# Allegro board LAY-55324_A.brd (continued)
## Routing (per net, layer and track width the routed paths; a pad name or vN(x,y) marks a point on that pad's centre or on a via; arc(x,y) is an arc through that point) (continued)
GPIO_AD_B1_12_EXT: length 38.3
  TOP w0.102: v1(41.33,52.58) 40.24,52.58 J64.5 ; v1(74.93,49.4) J3.31
  BOTTOM w0.102: v1(74.93,49.4) 74.52,49.81 74.52,50.06 72.31,52.27 65.48,52.27 64.97,52.79 64.12,52.79 63.91,52.58 v1(41.33,52.58)
GPIO_AD_B1_13: length 21
  TOP w0.102: v1(147.37,49.28) 146.41,48.31 146.41,45.32 145.97,44.89 145.97,40.77 v1(145.97,39.88)
  TOP w0.127: U4.H11 v3(146.23,31.43)
  BOTTOM w0.102: J2.27 147.5,48.9 v1(147.37,49.28) ; v3(146.23,31.43) 146.46,31.66 146.46,32.41 147.02,32.97 147.02,38.84 v1(145.97,39.88)
GPIO_AD_B1_13_EXT: length 41.6
  TOP w0.102: v1(36.32,52.42) J64.9 ; v1(73.66,49.4) J3.27
  BOTTOM w0.102: v1(36.32,52.42) 36.72,52.02 63.53,52.02 63.75,51.79 71.27,51.79 v1(73.66,49.4)
GPIO_AD_B1_15: length 23.3
  TOP w0.102: v1(148.77,53.47) 149.23,53.01 149.23,48.34 149.12,48.23 149.12,46.18 149.43,45.87 149.43,44.88 148.87,44.32 148.44,44.32 147.47,43.36 147.47,39.11 147.42,39.06 147.42,39.05 147.4,39.02 147.4,37.11 147.2,36.92 U4.J14
  BOTTOM w0.102: J2.32 v1(148.77,53.47)
GPIO_AD_B1_15_EXT: length 41.2
  TOP w0.102: J3.32 74.93,53.87 74.07,54.74 38.07,54.74 37.54,54.2 J64.7
GPIO_B0_04: length 23.9
  TOP w0.102: SW62.2 v1(134.89,18.54) SW62.1 134.89,21.72 135.31,22.14 135.31,22.73 137.46,24.89 137.46,25.78 138.61,26.92 138.99,26.92 R37.2 140.63,27.56 141.9,28.83 142.87,28.83 143.2,29.15 U4.C8
  BOTTOM w0.102: 134.89,17.53 v1(134.89,18.54)
GPIO_B0_05: length 13.9
  TOP w0.102: J63.2 133.02,26.16 134.29,27.43 134.29,27.44 134.34,27.49 134.34,28.39 134.92,28.97 141.01,28.97 141.52,29.48 142.11,29.48 142.43,29.15 U4.B8
GPIO_B0_06: length 3.6
  TOP w0.102: R35.2 v1(140.51,28.45) 141,28.45 141.71,29.15 U4.A8
  BOTTOM w0.102: R35.2 v1(140.51,28.45)
GPIO_B0_07: length 3.4
  TOP w0.102: U4.A9 141.35,29.8 141.14,29.59 v1(140.51,29.59) R38.2
  BOTTOM w0.102: R38.2 v1(140.51,29.59)
GPIO_B0_08: length 4.5
  TOP w0.102: U4.B9 142.65,29.91 142.33,30.24 142.33,30.56 142.11,30.78 141.61,30.78 R36.2
GPIO_B0_09: length 20.3
  TOP w0.102: SW61.1 v1(134.89,38.23) 135.25,37.86 135.25,31.36 SW61.2 135.27,30.61 137.34,30.61 137.79,31.06 139.4,31.06 139.62,30.84 R42.2 140.77,30.48 141.12,30.13 142.11,30.13 142.31,29.93 142.31,29.66 142.49,29.48 142.98,29.48 U4.C9
  BOTTOM w0.102: C37.1 134.92,38.77 134.89,38.73 v1(134.89,38.23)
GPIO_B0_10: length 33.3
  TOP w0.102: R39.2 v1(140.51,33.78)
  TOP w0.127: U4.D9 v3(143.63,29.48)
  BOTTOM w0.102: v3(143.63,29.48) 142.66,29.48 141.99,30.15 141.99,31.7 141.15,32.53 140.83,33.3 v1(140.51,33.78) 139.09,35.2 137.04,35.2 133.17,31.34 133.17,16.23 R227.2
GPIO_B0_11: length 28.5
  TOP w0.102: v1(141.15,50.81) 140.47,50.13 139.92,50.13 139.45,49.66 139.45,49.1 137.46,47.12 137.46,45.27 136.19,44 136.19,32.77 136.72,32.25 139,32.25 R34.2 139.64,31.61 140.27,31.61 141.43,30.45 U4.A10
  BOTTOM w0.102: J2.8 v1(141.15,50.81)
GPIO_B0_11_EXT: length 33.4
  TOP w0.102: J3.8 67.31,51.05 v1(66.93,50.67) ; v1(66.93,35.05) 63.75,35.05 62.23,36.58 v1(52.58,36.58)
  BOTTOM w0.102: v1(66.93,50.67) v1(66.93,35.05) ; R235.2 v1(52.58,36.58)
GPIO_B0_12: length 10.3
  TOP w0.102: R41.2 v1(140.51,34.8) ; U4.C10 v3(143.63,30.13)
  BOTTOM w0.102: R78.2 140,34.8 v1(140.51,34.8) 141.15,34.16 141.15,33.43 141.35,32.95 142.39,31.9 142.39,30.07 142.71,29.75 143.25,29.75 v3(143.63,30.13)
GPIO_B0_13: length 7.9
  TOP w0.102: R31.2 v1(140.51,35.81)
  TOP w0.127: U4.D10 v3(143.63,30.78)
  BOTTOM w0.102: v1(140.51,35.81) 140.89,35.81 141.4,35.31 141.4,34.92 143.15,33.18 143.15,31.26 v3(143.63,30.78)
GPIO_B0_14: length 26.4
  TOP w0.102: R18.2 v1(140.51,36.83) 140.51,37.26 139.32,38.46 139.32,46.73 141.72,49.13 141.72,49.47 v1(143.05,50.81) ; U4.E10 v3(144.28,30.78)
  BOTTOM w0.102: J2.14 v1(143.05,50.81) ; v3(144.28,30.78) 144.09,30.97 143.98,30.97 143.61,31.33 143.61,33.22 141.76,35.08 141.76,35.59 v1(140.51,36.83)
GPIO_B0_14_EXT: length 47.9
  TOP w0.102: v1(65.91,21.46) 64.01,19.56 53.34,19.56 52.45,18.67 U213.2 ; v1(69.22,50.67) J3.14
  BOTTOM w0.102: v1(65.91,21.46) 65.91,27.56 68.96,30.61 68.96,49.53 69.22,49.78 v1(69.22,50.67)
GPIO_B0_15: length 17.2
  TOP w0.102: v1(142.16,35.25) 142.16,34.42 142.42,34.16 142.42,33.4 142.33,33.31 142.33,32.91 142.49,32.75 142.74,32.75 142.96,32.53 142.96,32.32 143.18,32.1 143.39,32.1 143.61,31.88 143.61,31.67 143.83,31.45 144.15,31.45 144.5,31.1 U4.E11
  BOTTOM w0.102: U214.3 v4(135.33,36.01) 135.88,36.01 137.87,38 139.85,38 140.51,37.34 140.89,37.34 R77.2 v1(142.16,35.25)
GPIO_B1_00: length 60.3
  TOP w0.102: R224.2 v1(161.72,8.89) ; v1(140.51,32.64) 141.02,32.13 141.02,31.87 141.79,31.1 U4.A11
  BOTTOM w0.102: v1(140.51,32.64) 138.96,34.19 136.6,34.19 133.91,31.5 133.91,20.57 137.46,17.02 137.46,9.78 138.1,9.14 139.9,9.14 140.84,8.2 145.62,8.2 146.18,8.76 147.02,8.76 147.57,8.2 160.15,8.2 160.83,8.89 v1(161.72,8.89)
GPIO_B1_02: length 24.3
  TOP w0.102: v1(141.15,49.27) 138.94,47.06 138.94,45.19 137.46,43.71 137.46,39.24 v1(139.12,37.59) ; U4.C11 v3(142.98,30.78)
  BOTTOM w0.102: J2.7 v1(141.15,49.27) ; v1(139.12,37.59) 139.83,36.88 139.83,35.71 140.23,35.31 140.61,35.31 141.55,34.37 141.55,33.52 141.77,33.01 142.72,32.05 142.72,31.03 v3(142.98,30.78)
GPIO_B1_02_EXT: length 29.2
  TOP w0.102: J64.3 42.62,51.49 43.81,50.29 46.35,50.29 47.68,51.61 63.83,51.61 65.91,49.53 66.95,49.53 67.31,49.17 J3.7
GPIO_B1_03: length 20.8
  TOP w0.102: v1(141.08,46.48) 139.76,45.16 139.76,38.62 140.92,37.46 140.92,32.93 141.35,32.5 141.35,31.97 141.88,31.45 143.5,31.45 143.85,31.1 U4.D11
  BOTTOM w0.102: J2.9 141.78,46.58 141.68,46.48 v1(141.08,46.48)
GPIO_B1_03_EXT: length 35.7
  TOP w0.102: v1(67.94,45.97) J3.9 ; J64.4 43.18,46.52 43.18,45.39 43.28,45.29 54.02,45.29 57.51,41.81 64.07,41.81 65.34,40.54 v1(67.69,40.54)
  BOTTOM w0.102: v1(67.94,45.97) 67.94,42.67 67.69,42.42 v1(67.69,40.54)
I2C1_SCL: length 22.2
  TOP w0.102: v1(149.66,49.4) 150.16,48.9 150.16,44.12 149.53,43.48 149.53,41.81 148.95,41.23 v2(148.64,40.77)
  TOP w0.127: U4.J11 v3(147.53,31.43)
  BOTTOM w0.102: v1(149.66,49.4) 149.4,49.15 J2.33 ; v3(147.53,31.43) 147.95,31.85 147.95,40.08 v2(148.64,40.77) R16.2
I2C1_SCL_EXT: length 51.6
  TOP w0.102: v1(74.14,39.75) 73.69,39.29 65.07,39.29 63.63,40.74 57.06,40.74 53.58,44.22 36.85,44.22 35,46.08 J64.10 ; v1(75.31,45.97) 75.56,46.23 J3.33
  BOTTOM w0.102: v1(74.14,39.75) 74.14,40.77 74.45,41.07 74.45,41.23 75.06,41.84 75.06,45.36 v1(75.31,45.97)
I2C1_SDA: length 20.4
  TOP w0.102: U4.K11 v3(147.53,30.78) ; v1(150.67,46.61) 150.67,44.04 149.91,43.28 149.91,41.66 149.16,40.91 149.16,38.37 v2(148.64,37.85)
  BOTTOM w0.102: v3(147.53,30.78) 148.15,30.78 148.69,31.32 148.69,35.71 148.89,35.92 148.89,37.59 v2(148.64,37.85) R15.2 ; J2.37 v1(150.67,46.61)
I2C1_SDA_EXT: length 55.9
  TOP w0.102: v1(76.2,45.97) 76.45,45.97 76.83,46.36 J3.37 ; J64.12 32.46,46.15 34.75,43.87 53.44,43.87 56.92,40.39 63.48,40.39 64.93,38.94 74.63,38.94 v1(74.85,39.17)
  BOTTOM w0.102: v1(74.85,39.17) 75.31,39.62 75.31,41.02 75.82,41.53 75.82,45.09 76.2,45.47 v1(76.2,45.97)
JTAG_NTRST: length 19.5
  TOP w0.102: v1(145.09,38.43) 145.09,42.3 145.29,42.49 145.29,43.36 144.96,43.69 144.96,45.54 145.47,46.05 v1(145.47,46.61)
  TOP w0.127: U4.G10 v3(145.58,30.78)
  BOTTOM w0.102: v1(145.09,38.43) 145.09,37.81 146.23,36.68 146.23,33.02 145.9,32.69 145.9,32 145.58,31.68 v3(145.58,30.78) ; J2.23 146.23,46.74 146.1,46.61 v1(145.47,46.61)
JTAG_NTRST_EXT: length 64.9
  TOP w0.102: v1(72.01,49.4) 72.39,49.02 J3.23 ; v1(72.14,41.27) 71.35,40.49 70.09,40.49 69.1,41.48 65.4,41.48 64.36,42.52 57.94,42.52 57.28,43.18 57.28,43.18 51.33,49.12 23.76,49.12 23.15,48.51 J62.9
  BOTTOM w0.102: v1(72.14,41.27) 71.5,41.91 71.5,47.5 72.01,48.01 v1(72.01,49.4)
JTAG_TDI: length 16.6
  TOP w0.102: U4.F14 145.25,33.69 145.36,33.8 145.36,34.53 144.93,34.97 144.93,36.15 144.81,36.27 144.81,37.55 144.12,38.24 144.12,41.15 143.31,41.96 143.31,44.97 144.58,46.24 v1(144.58,46.61)
  BOTTOM w0.102: J2.19 144.96,46.71 144.86,46.61 v1(144.58,46.61)
JTAG_TDI_EXT: length 57.4
  TOP w0.102: v1(71.12,49.4) J3.19 ; v1(20.57,54.61) 20.57,52.58
  BOTTOM w0.102: v1(71.12,49.4) 71.12,50.98 70.82,51.28 23.9,51.28 v1(20.57,54.61)
JTAG_TDO: length 23.9
  TOP w0.102: U4.G13 145.9,32.51 146.25,32.85 146.25,35.16 146.05,35.36 146.05,37.49 146.23,37.67 146.23,39.37 146.41,39.55 146.41,44.7 146.76,45.06 146.76,47.9 147.88,49.02 147.88,49.94 148.34,50.39 148.34,51.31 147.88,51.77 v1(147.88,53.47)
  BOTTOM w0.102: v1(147.88,53.47) 148.13,53.21 J2.30
JTAG_TDO_EXT: length 70.8
  TOP w0.102: J3.30 74.3,50.93 v1(74.55,50.67) ; v1(74.55,42.42) 74.04,42.93 64.96,42.93 64.66,43.23 58.37,43.23 51.77,49.83 23.7,49.83 22.96,50.57 20.32,50.57 19.3,51.59 19.3,52.58
  BOTTOM w0.102: v1(74.55,50.67) 75.44,49.79 75.44,48.9 74.8,48.26 74.8,45.75 74.7,45.5 74.7,43.08 74.55,42.93 v1(74.55,42.42)
MIC_CLK_EXT: length 31.1
  BOTTOM w0.102: J2.70 160.83,50.98 160.5,50.65 158.95,50.65 158.19,49.89 150.96,49.89 150.3,50.55 148.62,50.55 148.01,49.94 139.69,49.94 137.51,47.75 134.67,47.75 134.29,48.13 R223.1
MIC_CLK_EXT_E: length 52.5
  TOP w0.102: v1(87.25,50.67) 86.99,50.93 J3.70 ; R222.1 R365.2 53.85,40.77 55.04,39.57 63.29,39.57 64.63,38.23 76.96,38.23 77.72,38.99 v1(87.25,38.99)
  BOTTOM w0.102: v1(87.25,50.67) 87.25,50.16 88.16,49.25 88.16,42.93 88.65,42.44 88.65,41.53 88.16,41.05 88.16,39.9 v1(87.25,38.99)
MIC_DATA0_EXT: length 44.5
  TOP w0.102: R225.1 160.83,15.94 160.26,16.51 160.26,20 160.83,20.57 163.12,20.57 163.67,21.12 163.67,46.31 161.27,48.71 161.27,51.76 v1(159.56,53.47)
  BOTTOM w0.102: J2.66 v1(159.56,53.47)
MIC_DATA0_EXT_E: length 97
  TOP w0.102: v1(87.25,40.01) 86.74,39.5 77.39,39.5 76.48,38.58 64.78,38.58 63.43,39.93 56.59,39.93 53.09,43.43 34.27,43.43 32.47,45.24 22.4,45.24 21.67,45.97 16.64,45.97 14.12,48.49 14.12,51.59 14.02,51.69 R243.2 R368.2 ; v1(85.98,50.67) 85.72,50.93 J3.66
  BOTTOM w0.102: v1(87.25,40.01) 87.63,40.39 87.63,49.28 86.94,49.96 86.69,49.96 v1(85.98,50.67)
MIC_DATA1_EXT: length 74.2
  TOP w0.102: v1(133.61,51.99) 133.61,48.8 134.16,48.25 134.16,45.64 132.64,44.12 132.64,39.56 132.61,39.54 132.61,39.2 132.64,39.18 132.64,38.1 132.72,38.02 132.72,36.84 132.64,36.76 132.64,27.29 131.42,26.08 131.42,21.8 132.36,20.86 132.36,10.71 133.27,9.8 v1(133.27,8.89)
  BOTTOM w0.102: R229.1 v1(133.27,8.89) ; J2.64 158.93,51.13 158.04,50.24 151.1,50.24 150.44,50.9 148.47,50.9 147.86,50.29 139,50.29 137.31,51.99 v1(133.61,51.99)
MIC_DATA1_EXT_E: length 113.6
  TOP w0.102: R367.2 R228.2 8.25,6.73 8.25,6.98 8.51,7.24 8.89,7.24 16.56,14.91 54.79,14.91 58.8,18.92 64.26,18.92 65.94,20.6 68.4,20.6 68.53,20.47 69.37,20.47 69.49,20.6 73.79,20.6 76.5,23.32 80.85,23.32 v1(82.8,25.27) ; v1(85.09,50.67) J3.64
  BOTTOM w0.102: v1(85.09,50.67) 85.72,50.04 85.72,47.44 86.44,46.73 86.44,41.2 86.6,41.04 86.6,29.07 v1(82.8,25.27)
MIKROBUS_PWM: length 18.1
  TOP w0.102: v1(142.37,46.53) 140.47,44.62 140.47,41.14 142.34,39.27 142.34,36.09 142.96,35.47 142.96,32.85 143.3,32.51 U4.C13
  BOTTOM w0.102: J2.13 142.98,47.86 142.98,46.66 142.84,46.53 v1(142.37,46.53)
MIKROBUS_PWM_EXT: length 34.9
  TOP w0.102: J3.13 69.22,46.23 v1(69.47,45.97) ; v1(69.47,40.54) 68.88,41.12 65.26,41.12 64.22,42.16 57.8,42.16 57.24,42.72 57.23,42.72 54.11,45.85 45.26,45.85 45.16,45.95 J64.2
  BOTTOM w0.102: v1(69.47,40.54) v1(69.47,45.97)
MODE0: length 3.6
  TOP w0.102: v1(135.56,24.51) J63.3
  BOTTOM w0.102: R65.2 v1(135.56,24.51)
MODE1: length 3.6
  TOP w0.102: v1(130.48,24.51) J63.1
  BOTTOM w0.102: R70.2 v1(130.48,24.51)
MQS_LEFT: length 29.2
  TOP w0.102: v1(137.08,31.75) 136.53,31.75 135.84,32.44 135.84,44.15 136.96,45.26 v1(136.96,45.85) ; U4.E7 144.26,28.16 143.83,28.16 143.65,27.98 143.65,27.77 143.41,27.53 v3(142.98,27.53)
  BOTTOM w0.102: v1(137.08,31.75) 137.79,31.04 139.9,31.04 141.02,29.92 141.02,29.49 v3(142.98,27.53) ; J2.1 139.24,46.93 139.08,46.76 137.87,46.76 v1(136.96,45.85)
MQS_LEFT_EXT: length 66.7
  TOP w0.102: J3.1 65.41,45.59 66.12,44.88 77.81,44.88 78.72,43.97 87.22,43.97 88.8,42.39 88.8,40.74 v1(89.66,39.88)
  BOTTOM w0.102: v1(89.66,39.88) 89.28,39.5 89.28,5.59 89.98,4.89 90.83,4.89 90.93,4.99 R43.2
MQS_RIGHT: length 27.3
  TOP w0.102: v1(137.97,45.85) 137.97,45.27 136.7,44 136.7,34.16 136.55,34.01 136.55,33.17 v1(136.96,32.77) ; v3(142.98,28.18) 143.52,28.18 143.77,28.43 U4.D7
  BOTTOM w0.102: v1(137.97,45.85) 138.51,46.39 140.23,46.39 140.51,46.67 J2.5 ; v3(142.98,28.18) 141.35,29.81 141.35,30.33 140.08,31.6 138.91,31.6 138.3,32.21 137.52,32.21 v1(136.96,32.77)
MQS_RIGHT_EXT: length 66.9
  TOP w0.102: J3.5 66.67,45.59 67.03,45.24 77.95,45.24 78.87,44.32 87.37,44.32 89.15,42.54 89.15,41.15 89.41,40.89 v1(89.66,40.89)
  BOTTOM w0.102: R44.2 90.93,4.34 90.83,4.45 89.79,4.45 88.82,5.42 88.82,40.05 v1(89.66,40.89)
NVCC_SEMC_1V8_3V3: length 1.7
  TOP w0.254: U4.E6 v3(144.93,27.53) ; U4.F5 v3(144.93,26.88)
  BOTTOM w0.254: C98.1 144.76,26.3 144.93,26.46 v3(144.93,26.88)
  vias: v4(142.6,26.21)
OUT+: length 2.6
  BOTTOM w0.508: U6.C3 99.24,6.53 99.75,6.53 FB3.1
OUT-: length 2.6
  BOTTOM w0.508: U6.A3 99.21,2.64 99.73,2.64 FB4.1
OUTN: length 4.6
  BOTTOM w0.508: TP61.1 102.71,3.87 C32.1 101.27,3.8 FB4.2
OUTP: length 14.2
  BOTTOM w0.508: FB3.2 101.27,5.34 C31.1 106.11,5.27 108.2,3.17 TP63.1
POR_B: length 59.7
  TOP w0.102: v1(135.61,45.85) 135.94,46.18 135.94,46.75 136.92,47.73 137.41,47.73 138.94,49.26 138.94,49.75 139.88,50.69 v1(139.88,50.81) ; TP214.1 156.9,37.49 155.88,38.5 v1(155.88,41.55)
  TOP w0.127: U4.M7 v3(148.83,28.18)
  BOTTOM w0.102: C4.1 R1.1 ; R1.1 135.69,44.55 135.61,44.63 v1(135.61,45.85) ; R1.1 149.1,43.94 151.49,41.55 v1(155.88,41.55) ; R69.2 157.82,35.52 TP214.1 ; v3(148.83,28.18) 148.83,27.63 149.73,26.72 151.56,26.72 152.4,27.56 155.22,27.56 156.24,28.57 156.24,28.62 157.53,29.91 157.53,34.01 156.9,34.65 TP214.1 ; C74.1 157.75,37.08 157.53,37.08 TP214.1 ; J2.4 v1(139.88,50.81)
POR_B_E: length 48.8
  TOP w0.102: v1(66.04,54.1) J3.4 ; v1(22.66,54.86) TP1.1 21.84,52.58
  BOTTOM w0.102: v1(66.04,54.1) 65.86,54.28 45.95,54.28 45.59,53.92 23.6,53.92 v1(22.66,54.86)
PSRAM_CLK: length 12.2
  TOP w0.102: U4.D2 143.62,24.92 143.62,24.23 143.52,24.13 143.13,24.13 141.82,22.83 141.82,22.68 141.94,22.56 142.09,22.56 143.17,23.64 143.87,23.64 143.98,23.54 143.98,23.4 143.7,23.12 143.7,22.87 144.03,22.54 144.03,22.39 144.13,22.28 144.25,22.28 144.36,22.18 144.36,21.98 144.25,21.88 143.71,21.88 143.61,21.78 143.61,21.46 143.71,21.36 v1(144.59,21.36)
  BOTTOM w0.102: R277.2 R279.1 v1(144.59,21.36)
PSRAM_DATA0: length 11
  TOP w0.102: U4.B3 142.34,25.59 141.76,25.59 141.33,25.16 141.15,24.71 139.7,21.22 139.18,20.7 139.18,19.95 139.32,19.62 v1(140.59,18.36)
  BOTTOM w0.102: R264.1 v1(140.59,18.36)
  BOTTOM w0.127: R265.1 v1(140.59,18.36)
PSRAM_DATA1: length 9.6
  TOP w0.102: U4.A2 141.76,25.25 141.66,25.15 141.66,25.02 141.76,24.92 142.78,24.92 142.97,24.74 142.97,24.42 141.92,23.37 141.69,23.37 141.58,23.27 141.58,23.03 141.02,22.47 141.02,21.95 141.12,21.84 141.4,21.84 141.76,22.21 141.97,22.21 142.09,22.09 142.09,21.47 141.99,21.37 v1(141.6,21.37)
  BOTTOM w0.102: R273.1 141.6,21.37 v1(141.6,21.37) R266.1
PSRAM_DATA2: length 12.8
  TOP w0.102: U4.D1 143.95,24.29 144.54,22.86 145.01,21.74 145.01,20.95 145.49,19.8 146,18.57 146,17.27 145.89,17.01 145.36,16.48 144.98,16.48 144.59,16.87 v1(144.59,17.36)
  BOTTOM w0.102: R274.1 144.1,15.59 R267.1
  BOTTOM w0.127: R267.1 144.1,16.87 v1(144.59,17.36)
PSRAM_DATA3: length 12.9
  TOP w0.102: U4.E1 145.31,22.9 145.34,22.87 145.67,22.07 145.67,21 145.76,20.79 146.1,20.45 146.33,19.89 146.33,17.22 146.17,16.83 145.47,16.13 144.85,16.13 v1(143.59,16.36)
  BOTTOM w0.102: R275.1 143.6,15.2 R268.1
  BOTTOM w0.127: R268.1 143.6,16.35 v1(143.59,16.36)
PSRAM_DATA4: length 13.5
  TOP w0.102: U4.A6 141.52,27.65 140.66,26.8 138.58,21.76 138.58,19.38 v1(139.59,16.36)
  BOTTOM w0.127: R269.1 139.59,16.36 v1(139.59,16.36)
PSRAM_DATA5: length 11
  TOP w0.102: U4.B6 142.44,27.64 142.19,27.54 142.01,27.54 141.83,27.46 140.97,26.6 138.93,21.69 138.93,19.63 v1(139.27,19.05)
  BOTTOM w0.102: R270.1 v1(139.27,19.05)
PSRAM_DATA6: length 8.8
  TOP w0.102: v1(139.59,20.36) 139.59,19.85 139.86,19.59 140,19.59 140.16,19.75 140.16,20.56 139.87,20.85 139.87,20.99 140.16,21.28 140.16,21.54 140.66,22.05 140.66,22.61 141.3,23.25 141.3,23.39 141.12,23.57 141.12,23.72 141.26,23.86 141.41,23.86 141.59,23.68 141.73,23.68 U4.B1
  BOTTOM w0.127: R271.1 139.59,20.35 v1(139.59,20.36)
PSRAM_DATA7: length 8.7
  TOP w0.102: v1(139.34,21.6) 139.34,21.67 139.6,22.3 139.8,22.38 139.9,22.64 139.82,22.84 139.92,23.07 140.12,23.16 140.2,23.37 140.12,23.56 140.23,23.83 140.39,23.89 140.5,24.15 140.43,24.31 140.54,24.58 140.7,24.64 140.81,24.91 140.74,25.07 141.05,25.79 141.18,25.85 141.49,25.72 141.63,25.77 141.7,25.96 141.65,26.09 141.33,26.22 141.28,26.36 141.37,26.57 141.72,26.92 141.94,26.92 142,26.99 U4.A5
  BOTTOM w0.127: R272.1 v1(139.34,21.6)
PSRAM_DQS: length 8.8
  TOP w0.102: U4.G2 145.6,24.95 145.6,24.49 145.36,24.26 145.36,23.75 145.52,23.6 145.84,23.6 146.08,23.36 146.08,23.13 145.87,22.93 145.87,22.73 146.08,22.52 v1(146.08,21.08)
  BOTTOM w0.127: R281.1 143.8,19.58 145.12,20.12 v1(146.08,21.08)
PSRAM_RST_N: length 5.1
  TOP w0.102: U215.A4 v1(145.59,17.36)
  BOTTOM w0.102: v2(146.84,14.36) 146.84,14.84 147.09,15.09 147.09,15.54 146.86,16.1 R288.2
  BOTTOM w0.127: C277.1 145.1,16.87 v1(145.59,17.36) 146.08,16.87 R288.2
PSRAM_SS0: length 9.8
  TOP w0.102: U4.D3 144.18,25.9 144.29,25.8 144.29,24.45 144.39,24.2 144.54,24.14 144.65,23.87 144.59,23.72 145.32,21.94 145.32,21.06 145.59,20.4 v1(145.92,19.81)
  BOTTOM w0.102: v1(145.92,19.81) 146.13,20.02 146.45,20.02 146.61,19.86 146.61,19.39 R278.1 R276.2
QSPI_CLK: length 14.7
  TOP w0.102: v1(155.24,17.53) TP66.1 155.24,21.59 153.97,22.86 153.97,24.41 152.98,25.4 151.82,25.4 150.98,26.24 148.82,26.24 U4.L4
  BOTTOM w0.102: U5.6 v1(155.24,17.53)
QSPI_DQ0: length 15.4
  TOP w0.102: v1(156.51,17.53) 155.7,16.71 153.9,16.71 153.34,17.27 153.34,24.54 152.84,25.03 151.68,25.03 150.81,25.9 U4.P3
  BOTTOM w0.102: U5.5 v1(156.51,17.53)
QSPI_DQ1: length 6.5
  TOP w0.102: U4.N4 150.15,26.9 151.15,26.9 151.16,26.89 151.35,26.89 152.07,26.16 153.59,26.16 v1(154.36,25.4)
  BOTTOM w0.102: v1(154.36,25.4) 153.97,25.02 U5.2
QSPI_DQ3_HOLDN: length 18.5
  TOP w0.102: v1(153.97,17.53) 154.43,17.07 155.43,17.07 155.88,17.52 155.88,25.4 154.76,26.52 152.22,26.52 151.49,27.24 151.15,27.24 151.11,27.2 U4.P5
  BOTTOM w0.102: R30.2 U5.7 v1(153.97,17.53)
QSPI_SN: length 5.6
  TOP w0.102: R17.2 152.67,24.35 v1(151.94,24.35) 151.59,24.56 150.59,25.56 148.85,25.56 U4.L3
  BOTTOM w0.102: v1(151.94,24.35) U5.1
QSPI_WN_DQ2: length 7.8
  TOP w0.102: U4.P4 151.17,26.55 151.92,25.81 153.14,25.81 154.05,24.89 154.74,24.89 v1(155.24,25.4) R14.2
  BOTTOM w0.102: U5.3 v1(155.24,25.4)
R: length 3.5
  TOP w0.102: D60.2 v1(164,16.26)
  BOTTOM w0.102: R80.2 163.5,18.03 164,17.53 v1(164,16.26)
RF_50E: length 2.2
  TOP w0.635: J1.1 D1.2 R2.1
RGB_LED_B: length 44
  TOP w0.102: v1(152.35,41.02) 152.35,40.41 151.87,39.93 151.87,38.77 150.7,37.6 150.7,36.68 148.81,34.79 148.81,30.98 148.63,30.8 148.33,30.8 148.04,30.51 147.91,30.51 U4.K10
  BOTTOM w0.102: R81.1 161.34,18.92 v2(160.96,19.3) 160.96,21.72 162.05,22.81 162.05,27.76 161.07,28.74 161.07,39.03 159.08,41.02 v1(152.35,41.02)
RGB_LED_G: length 48.3
  TOP w0.102: v1(148.13,41.66) 147.83,41.35 147.83,38.96 147.78,38.91 147.78,38.9 147.75,38.88 147.75,36.93 147.53,36.39 147.53,32.89 147.34,32.7 147.33,32.71 147.08,32.71 146.9,32.53 146.9,32.06 U4.J12
  BOTTOM w0.102: v1(148.13,41.66) 149.43,41.66 151.21,39.88 152.28,39.88 152.48,40.08 158.37,40.08 159.64,38.81 159.64,27.66 161.19,26.11 161.19,23.98 159.94,22.73 159.94,17.78 v2(160.96,16.76) 161.34,17.14 R82.1
RGB_LED_R: length 43.1
  TOP w0.102: v1(151.15,40.51) 151.15,39.06 149.99,37.89 149.99,37.09 148.18,35.29 148.18,32.08 U4.K12
  BOTTOM w0.102: v1(151.15,40.51) 158.7,40.51 160.26,38.95 160.26,28.36 161.59,27.03 161.59,23.5 160.45,22.35 160.45,18.54 v2(160.96,18.03) R80.1
RTC_XTALI: length 26.8
  TOP w0.102: v1(153.85,50.81) 155.98,48.68 155.98,44.98 155.32,44.32 155.32,38.56 156.24,37.64 156.24,37.16 155.93,36.86 155.93,35.84 157.78,33.99 157.78,31.12 157.02,30.35 156.01,30.35 155.75,30.61 R12.1
  BOTTOM w0.102: J2.48 v1(153.85,50.81)
RTC_XTALI_EXT: length 59.2
  TOP w0.102: v1(39.24,39.75) 43.56,39.75 44.09,39.22 63.14,39.22 64.49,37.87 78,37.87 v1(78.49,38.35) ; J3.48 80.01,53.72 v1(79.63,54.1)
  BOTTOM w0.102: v1(78.49,38.35) 78.49,41.35 78.66,41.53 78.66,44.28 79.12,44.73 79.12,53.6 v1(79.63,54.1) ; R293.1 v1(39.24,39.75)
RTC_XTALI_M2: length 31.7
  TOP w0.102: v1(35.94,39.12) 33.86,39.12 32.28,40.69 32.28,43.54 31.67,44.15 22.4,44.15 20.98,45.57 18.26,45.57 14.86,42.16 R322.2 R10.2
  BOTTOM w0.102: R316.1 36.63,38.68 36.19,38.86 v1(35.94,39.12) 36.4,39.57 R293.2
SAI1_RX_BCLK_A: length 71.8
  TOP w0.102: R221.2 v1(129.34,9.14) 128.8,9.68 128.8,43.54 v1(129.59,44.32)
  BOTTOM w0.102: R362.2 160.93,7.85 147.4,7.85 146.97,7.67 146.43,7.67 146,7.85 140.7,7.85 139.81,8.74 136.29,8.74 136.06,8.51 135.08,8.51 134.7,8.89 134.04,8.89 133.53,8.38 133.02,8.38 132.51,8.89 131.62,8.89 131.37,9.14 v1(129.34,9.14) ; v1(129.59,44.32) 130.23,44.96 R49.1
SAI1_RX_BCLK_A_EXT: length 147.3
  TOP w0.102: R222.2 v1(49.78,42.29)
  BOTTOM w0.102: R245.2 v1(12.43,49.26) 13.48,49.26 19.05,43.69 28.63,43.69 31.22,41.1 31.22,38.91 29.46,37.16 29.46,30.45 29.57,30.35 29.57,25.43 19.94,15.8 13.51,15.8 6.07,8.36 6.07,5.14 R254.2 6.96,5.23 6.96,8.51 13.18,14.73 16.13,14.73 16.54,15.14 40.67,15.14 46.02,20.5 46.02,35.08 47.09,36.14 47.09,36.83 48.54,38.28 48.54,41.1 49.73,42.29 v1(49.78,42.29)
SD1_CLK: length 57.8
  TOP w0.102: v1(157.66,50.81) 159.05,49.41 159.05,45.59 160.03,44.62 160.03,27.14 158.24,25.35 158.24,16.54 156.95,15.24 150.64,15.24 150.61,15.27 150.6,15.27 147.18,18.69 147.18,20.15 146.86,20.47 146.86,25.52 147.2,25.87 U4.J3
  BOTTOM w0.102: J2.60 v1(157.66,50.81)
SD1_CLK_EXT: length 81.7
  TOP w0.102: v1(83.44,36.96) 82.98,36.96 82.42,37.52 79.71,37.52 79,36.8 64.01,36.8 62.67,38.15 44.5,38.15 43.05,36.7 27.05,36.7 23.49,33.15 R20.1 ; v1(83.82,50.67) J3.60
  BOTTOM w0.102: v1(83.44,36.96) 84.12,37.64 84.63,37.64 84.84,37.85 84.84,38.61 84.58,38.86 84.58,45.02 84.2,45.4 84.2,46.46 84.58,46.84 84.58,49.91 v1(83.82,50.67)
SD1_CMD: length 38.7
  TOP w0.102: v1(155.12,50.81) 155.12,50.04 156.9,48.26 156.9,45.82 156.77,45.69 156.77,41.73 158.61,39.89 158.61,28.1 157.13,26.62 156.84,26.62 v1(156.51,26.29)
  TOP w0.127: U4.J4 v3(147.53,26.23)
  BOTTOM w0.102: v1(156.51,26.29) 155.96,26.85 152.96,26.85 152.12,26.01 148.62,26.01 148.44,25.83 147.96,25.83 147.56,26.23 v3(147.53,26.23) ; J2.52 v1(155.12,50.81)
SD1_CMD_EXT: length 82.2
  TOP w0.102: J3.52 81.28,50.29 v1(81.53,50.04) ; v1(80.14,36.96) 79.63,36.45 63.87,36.45 62.52,37.8 47.32,37.8 46.61,37.08 46.61,33.66 43.81,30.86 27.76,30.86 26.62,29.72 24.59,29.72 23.44,30.86 v1(22.99,30.86) R29.2
  BOTTOM w0.102: v1(80.14,36.96) 81.05,37.87 81.05,45.55 81.31,45.81 81.31,46.51 82.04,47.24 82.04,49.53 v1(81.53,50.04) ; R76.2 v1(22.99,30.86)
SD1_DATA0: length 51.3
  TOP w0.102: v1(158.55,46.61) 158.55,45.23 157.88,44.57 157.88,42.57 159.67,40.77 159.67,27.41 157.84,25.58 157.84,16.74 156.72,15.62 150.75,15.62 147.48,18.89 147.48,20.35 147.29,20.53 147.29,22.93 147.2,23.02 U4.J1
  BOTTOM w0.102: v1(158.55,46.61) 158.83,46.61 158.93,46.71 J2.63
SD1_DATA0_EXT: length 81.4
  TOP w0.102: v1(84.58,36.96) 83.99,37.55 83.02,37.55 82.68,37.9 79.59,37.9 78.86,37.16 64.16,37.16 62.81,38.51 43.97,38.51 43.31,37.85 24,37.85 23.69,37.53 23.69,36.13 v1(22.99,35.43) R25.2 ; v1(85.09,49.4) J3.63
  BOTTOM w0.102: R73.2 v1(22.99,35.43) ; v1(85.09,49.4) 85.09,46.61 85.22,46.48 85.22,37.59 v1(84.58,36.96)
SD1_DATA1: length 48.4
  TOP w0.102: U4.K1 147.85,23.33 148.01,23.17 148.01,20.83 148.19,20.64 148.19,19.27 151.1,16.36 156.13,16.36 157.02,17.25 157.02,26.01 158.96,27.95 158.96,40.22 157.12,42.05 157.12,45.17 157.4,45.45 v1(157.4,46.61)
  BOTTOM w0.102: J2.59 157.66,46.86 v1(157.4,46.61)
SD1_DATA1_EXT: length 76.6
  TOP w0.102: v1(83.82,49.4) J3.59 ; R19.2 v1(22.99,37.72) 23.49,38.23 42.04,38.23 42.68,38.86 62.99,38.86 64.34,37.52 78.71,37.52 79.55,38.35 v1(83.31,38.35)
  BOTTOM w0.102: v1(83.82,49.4) 83.82,46.58 83.85,46.56 83.85,38.89 v1(83.31,38.35) ; R72.2 v1(22.99,37.72)
SD1_DATA2: length 53.7
  TOP w0.102: v1(159.56,46.61) 159.56,45.7 160.38,44.88 160.38,26.86 158.67,25.15 158.67,16.43 157.1,14.86 150.37,14.86 146.86,18.37 146.86,20.08 146.48,20.46 146.48,24.24 146.25,24.48 146.25,24.79 146.55,25.09 U4.H2
  BOTTOM w0.102: J2.65 v1(159.56,46.61)
SD1_DATA2_EXT: length 83.1
  TOP w0.102: v1(85.72,45.97) J3.65 ; R27.2 v1(22.99,26.29) 26.16,26.29 29.97,30.1 40.19,30.1 40.6,29.69 40.94,29.69 41.34,30.1 44.06,30.1 47.32,33.36 47.32,34.24 48.01,34.92 48.01,36.83 48.26,37.08 62.22,37.08 63.57,35.74 84.51,35.74 v1(85.72,36.96)
  BOTTOM w0.102: v1(85.72,45.97) 85.98,45.72 85.98,37.21 v1(85.72,36.96) ; R75.2 v1(22.99,26.29)
SD1_DATA3: length 55.3
  TOP w0.102: v1(156.39,50.81) 157.66,49.54 157.66,47.15 158.04,46.77 158.04,45.49 157.51,44.96 157.51,42.31 159.32,40.5 159.32,27.8 157.43,25.92 157.43,16.94 156.49,16 150.93,16 147.84,19.09 147.84,20.5 147.65,20.68 147.65,23.02 147.51,23.17 147.51,24.76 147.2,25.06 U4.J2
  BOTTOM w0.102: J2.56 v1(156.39,50.81)
SD1_DATA3_EXT: length 83.8
  TOP w0.102: v1(82.17,36.96) 81.31,36.09 63.72,36.09 62.37,37.44 47.86,37.44 47.37,36.95 47.37,34.79 46.96,34.39 46.96,33.51 43.96,30.51 28.17,30.51 26.85,29.18 24.28,29.18 23.67,28.57 v1(22.99,28.57) R26.2 ; v1(82.55,50.67) J3.56
  BOTTOM w0.102: v1(82.17,36.96) 82.65,37.44 82.65,37.44 82.65,38.58 83.21,39.14 83.21,45.01 82.91,45.31 82.91,48.5 83.11,48.7 83.11,49.76 82.93,49.94 82.93,50.29 v1(82.55,50.67) ; R74.2 v1(22.99,28.57)
SHIELD: length 14
  BOTTOM w0.508: 95.32,49.85 CON60.SH2 96.14,51.17 ; 95.02,54.76 CON60.SH3 ; CON60.SH3 96.65,54.76 ; CON60.SH3 95.84,52.69 ; CON60.SH4 105.89,54.76 ; CON60.SH4 104.26,54.76 ; CON60.SH4 105.08,52.69 ; 104.78,51.17 CON60.SH1 105.59,49.85 ; 99.94,53.65 FB1.2 ; FB1.2 100.71,54.42 ; FB1.2 101.49,53.65
SWD_CLK/JCLK: length 25.8
  TOP w0.102: v1(146.23,53.47) 146.23,50.7 145.69,50.16 145.59,50.16 144.86,49.43 144.86,48.72 144.04,47.9 144.04,46.21 142.95,45.12 142.95,41.76 143.76,40.94 143.76,38.09 144.38,37.48 144.38,35.99 144.68,35.69 144.68,34.57 v1(144.96,34.29) ; U4.F12 v3(144.93,32.08)
  BOTTOM w0.102: J2.24 v1(146.23,53.47) ; v3(144.93,32.08) 145.39,32.54 145.39,33.86 v1(144.96,34.29)
SWD_CLK/JCLK_EXT: length 59.8
  TOP w0.102: 18.03,52.58 TP60.1 v1(18.85,54.86) ; v1(72.39,54.05) J3.24
  BOTTOM w0.102: v1(18.85,54.86) 19.3,55.32 21.08,55.32 23.29,53.11 71.45,53.11 v1(72.39,54.05)
SWD_DIO/TMS: length 16.7
  TOP w0.102: U4.E14 144.42,33.23 144.42,35.38 143.94,35.86 143.94,37.41 143.41,37.94 143.41,40.69 142.6,41.51 142.6,45.26 143.43,46.1 v1(143.43,46.61)
  BOTTOM w0.102: J2.17 144.22,47.84 144.22,46.89 143.94,46.61 v1(143.43,46.61)
SWD_DIO/TMS_EXT: length 68.5
  TOP w0.102: v1(70.64,41.02) 69.82,41.83 65.55,41.83 64.51,42.88 58.09,42.88 51.49,49.48 23.42,49.48 22.68,50.22 20.17,50.22 19.51,50.88 17.2,50.88 16.76,51.31 TP22.1 ; v1(70.74,45.97) 70.48,46.23 J3.17
  BOTTOM w0.102: v1(70.74,45.97) 70.74,45.02 70.64,44.92 v1(70.64,41.02)
USB_DM: length 24.3
  TOP w0.102: v1(153.92,45) 154.27,45 154.56,44.71 154.56,38.21 v1(154.3,37.95)
  TOP w0.127: v3(149.48,28.83) 149.15,29.15 U4.M8
  BOTTOM w0.102: J2.45 153.21,47.18 153.42,46.97 153.42,45.9 153.92,45.4 v1(153.92,45) ; v1(154.3,37.95) 154.56,37.68 154.56,33.91 153.77,33.13 153.77,30.63 153.14,30 151.05,30 150.57,29.51 150.57,29.24 150.16,28.83 v3(149.48,28.83)
USB_DM_EXT: length 28.7
  TOP w0.102: J3.45 79.38,46.24 79.45,46.16 79.45,45.52 79.89,45.09 91.03,45.09 92.2,43.92 101.23,43.92 v1(101.6,43.55)
  BOTTOM w0.102: v1(101.6,43.55) 101.23,43.92 100.73,43.92 100.33,44.32 100.33,45.64 100.18,45.8 L60.3
USB_DP: length 25.5
  TOP w0.102: v1(154.45,45.53) 154.45,45.18 154.81,44.82 154.81,38.19 v1(155.05,37.95)
  TOP w0.127: U4.L8 148.5,29.15 v3(148.83,28.83)
  BOTTOM w0.102: v1(155.05,37.95) 154.81,37.71 154.81,33.81 154.03,33.02 154.03,30.53 153.24,29.74 151.16,29.74 150.83,29.41 150.83,29.13 150.27,28.58 149.97,28.58 149.79,28.4 149.26,28.4 148.83,28.83 v3(148.83,28.83) ; v1(154.45,45.53) 154.14,45.53 153.67,46 153.67,46.99 153.85,47.16 J2.47
USB_DP_EXT: length 28
  TOP w0.102: J3.47 79.91,47.59 79.91,46.28 79.71,46.08 79.71,45.63 80,45.34 91.14,45.34 92.31,44.17 101.19,44.17 v1(101.6,44.58)
  BOTTOM w0.102: L60.2 100.74,45.8 100.58,45.64 100.58,44.42 100.84,44.17 101.19,44.17 v1(101.6,44.58)
USB_OTG1_VBUS: length 5.7
  TOP w0.127: U4.N6 v3(150.13,28.18)
  TOP w0.381: FB2.2 154.36,27.18 154.19,27.01 152.49,27.01 152.2,27.3 C11.1 152.15,27.74 v1(151.46,27.74)
  BOTTOM w0.254: v3(150.13,28.18) 150.15,28.16 C77.1
  BOTTOM w0.381: v1(151.46,27.74) 151.04,28.16 C77.1
WIFI_32K: length 1.3
  TOP w0.102: R10.1 12.44,44.45 Y1.3
WL_3V3: length 52
  TOP w0.305: 44.18,33.43 J8.74 ; 26.18,33.43 J8.2 ; 43.68,33.43 J8.72 ; 26.68,33.43 J8.4
  TOP w0.381: v1(12.08,29.7) 11.34,28.96 U2.9
  TOP w0.508: C7.1 11.46,24.73 C6.1 11.46,22.51 L1.2 14.16,22.29 16.76,19.68 v1(36.83,19.68) ; C7.1 TP5.1 ; C7.1 11.46,24.8 C20.1 11.43,25.94 C21.1 11.34,27.14 U2.9
  BOTTOM w0.305: C228.1 v1(44.45,33.29) ; C229.1 v1(43.56,33.29)
  BOTTOM w0.381: C231.1 v1(26.8,33.29) ; C230.1 v1(25.78,33.29) ; R357.1 14.99,35.81 14.48,35.31 14.48,30.48 14.1,30.1 12.48,30.1 v1(12.08,29.7)
  vias: v1(36.5,31.83) v1(37.41,31.83)
WL_HOST_RST_N: length 1.7
  TOP w0.102: J8.23 31.37,42.08 TP203.1
WL_HOST_WAKE: length 30.9
  TOP w0.102: v2(156.64,28.45) 158.2,30.01 158.2,39.57 156.39,41.39 v1(156.39,46.61)
  TOP w0.127: U4.L6 148.83,27.53 v3(148.83,26.88)
  BOTTOM w0.102: v2(156.64,28.45) 155.4,27.2 152.68,27.2 151.84,26.37 149.34,26.37 v3(148.83,26.88) ; J2.55 v1(156.39,46.61)
WL_HOST_WAKE_EXT: length 37.2
  TOP w0.102: v1(72.39,23.88) 79.88,23.88 v1(81.28,25.27) ; v1(82.55,49.4) J3.55
  BOTTOM w0.102: v1(72.39,23.88) R306.1 ; v1(81.28,25.27) 81.28,28.57 80.52,29.34 80.52,36.07 80.77,36.32 80.77,37.08 81.66,37.97 81.66,46.29 82.55,47.18 v1(82.55,49.4)
WL_HOST_WAKE_LS: length 55.8
  TOP w0.102: v1(16.13,30.35) 16.13,29.08 15.62,28.57 15.62,26.21 18.85,22.99 40.57,22.99 40.8,23.22 60.05,23.22 v1(60.45,23.62)
  BOTTOM w0.102: R296.2 v1(60.45,23.62) 60.69,23.86 U221.3 ; R336.1 R304.2 16.26,30.86 16.13,30.73 v1(16.13,30.35)
WL_REG_ON: length 21.1
  TOP w0.102: v1(151.94,46.61) 151.94,44.02 150.67,42.75 150.67,41.2 150.62,41.15 150.62,39.86 v1(150.42,39.37) ; U4.K7 v3(148.18,28.83)
  BOTTOM w0.102: J2.41 v1(151.94,46.61) ; v3(148.18,28.83) 148.97,29.62 148.97,30.4 149.35,30.78 149.35,34.44 150.14,35.22 150.14,38.33 150.42,38.61 v1(150.42,39.37)
WL_REG_ON_EXT: length 31.3
  TOP w0.102: v1(78.61,45.97) 78.36,45.97 78.11,46.23 J3.41 ; v2(72.64,24.77) 73.15,25.27 75.95,25.27 76.3,24.92 v1(78.08,24.92)
  BOTTOM w0.102: R318.1 v2(72.64,24.77) R309.1 ; v1(78.61,45.97) 78.61,44.73 78.31,44.42 78.31,41.68 78.13,41.5 78.13,39.01 77.98,38.86 77.98,38.02 78.08,37.92 v1(78.08,24.92)
WL_REG_ON_LS: length 50.8
  TOP w0.102: v1(60.45,24.64) 59.59,24.64 59.08,24.13 41.28,24.13 40.97,24.43 40.07,24.43 39.02,23.39 19.2,23.39 16.51,26.09 v1(16.51,27.56)
  BOTTOM w0.102: R341.1 16.26,27.81 v1(16.51,27.56) ; U221.4 61.09,24.51 60.96,24.64 v1(60.45,24.64) R308.2
WL_SD1_CLK: length 4
  TOP w0.102: R20.2 20.83,33.57 R330.2 v1(19.94,34.29) R329.1
  BOTTOM w0.102: R329.1 v1(19.94,34.29)
WL_SD1_CMD: length 4
  TOP w0.102: R328.1 v1(19.94,32) R331.2 20.83,31.28 R29.1
  BOTTOM w0.102: R328.1 v1(19.94,32)
WL_SD1_DATA0: length 4
  TOP w0.102: R324.1 v1(19.94,36.58) R332.2 20.83,35.85 R25.1
  BOTTOM w0.102: R324.1 v1(19.94,36.58)
WL_SD1_DATA1: length 4
  TOP w0.102: R325.1 v1(19.94,38.86) R333.2 20.83,38.14 R19.1
  BOTTOM w0.102: R325.1 v1(19.94,38.86)
WL_SD1_DATA2: length 4
  TOP w0.102: R27.1 20.83,26.71 R334.2 v1(19.94,27.43) R326.1
  BOTTOM w0.102: R326.1 v1(19.94,27.43)
WL_SD1_DATA3: length 4
  TOP w0.102: R26.1 20.83,28.99 R335.2 v1(19.94,29.72) R327.1
  BOTTOM w0.102: R327.1 v1(19.94,29.72)
N99781683: length 5.3
  TOP w0.102: R12.2 R11.1 153.37,30.19 Y3.1 152.45,30.07 150.95,30.07 150.91,30.11 150.11,30.11 U4.N9
N99781708: length 6.7
  TOP w0.102: U4.N11 149.91,31.1 150.02,31.22 150.23,31.43 150.66,31.43 150.72,31.37 152.12,31.37 152.53,31.78 R13.2 152.85,32.59 Y2.1 152.61,33.76 C23.1
N101568785: length 8.9
  TOP w0.102: U4.P11 150.67,31.01 152.27,31.01 152.81,31.56 R13.1 153.25,32.6 153.98,33.33 Y2.3 155.61,33.33 C19.1 R8.1
N101575953: length 3.8
  TOP w0.102: C22.1 153.58,29.09 Y3.2 152.31,29.09 151.82,29.59 150.67,29.59 U4.P9
N101577088: length 2.6
  TOP w0.127: U4.K3 v3(147.53,25.58)
  BOTTOM w0.254: R71.2 147.24,23.88 147.24,24.64 C86.1 v3(147.53,25.58)
N101638363: length 3.1
  TOP w0.102: TP14.1 150.13,34.04 150.18,33.99 150.18,33.39 150.13,33.33 150.13,32.24 149.8,31.92 U4.N12
N102042510: length 10.1
  TOP w0.102: SW60.2 134.89,43.65 135.05,43.81 v1(135.05,44.83) 135.05,51.83 SW60.1
  BOTTOM w0.102: R1.2 134.67,44.45 v1(135.05,44.83)
N102115004: length 9.1
  TOP w0.102: U4.M6 149.15,27.85 v3(149.48,27.53)
  BOTTOM w0.102: v2(156.64,29.72) 156.06,29.13 156.06,28.98 154.99,27.91 152.21,27.91 151.63,27.33 151.54,27.33 151.16,26.95 150.06,26.95 v3(149.48,27.53)
N102548232: length 3.1
  TOP w0.102: v1(150.29,9.65) J61.2
  BOTTOM w0.102: R62.1 v1(150.29,9.65)
N102553145: length 5.8
  TOP w0.102: R53.2 164.13,12.54 R226.1
N102553184: length 2
  TOP w0.102: R53.1 v1(164.52,6.1)
  BOTTOM w0.102: M1.1 164.03,5.33 164.03,5.61 v1(164.52,6.1)
N102553251: length 4.6
  TOP w0.102: R221.1 v1(129.34,6.1) 129.9,5.54 R249.1
  BOTTOM w0.102: M2.4 129.44,4.3 129.34,4.4 v1(129.34,6.1)
N102553371: length 5
  TOP w0.102: v1(133.15,7.44) 134.11,7.44 v1(135.69,9.02)
  BOTTOM w0.102: R244.2 v1(135.69,9.02) ; v1(133.15,7.44) R54.2
N102577756: length 14.6
  TOP w0.381: R303.1 v1(21.08,39.93)
  BOTTOM w0.381: v1(21.08,39.93) R72.1 R73.1 R76.1 R74.1 R75.1
N102592066: length 2.7
  BOTTOM w0.102: 93.6,2.67 C28.1 R46.1 R44.1
N102592074: length 0.9
  BOTTOM w0.102: C30.2 R48.2
N102592078: length 1.4
  BOTTOM w0.102: R48.1 96.52,3.81 U6.A1
N102592271: length 2.7
  BOTTOM w0.102: R43.1 R45.1 C27.1 93.6,6.6
N102592279: length 0.9
  BOTTOM w0.102: R47.2 C29.2
N102645166: length 1.1
  TOP w0.127: U4.F13 v3(144.93,32.73)
  BOTTOM w0.102: R33.1 144.95,32.75 v3(144.93,32.73)
N102680332: length 1.5
  BOTTOM w0.102: U6.C1 96.52,5.33 R47.1
N102764568: length 1.5
  BOTTOM w0.102: M2.1 132.26,5.69 R54.1
N102806355: length 2.3
  TOP w0.127: U4.P8 150.86,29.15 v3(151.18,28.83)
  BOTTOM w0.254: C69.1 151.56,29.21 v3(151.18,28.83) 151.56,28.45 C71.1
N102806363: length 2.4
  TOP w0.127: v3(151.05,30.61) 150.9,30.45 U4.P10
  BOTTOM w0.254: C80.1 151.56,31.24 151.05,30.73 v3(151.05,30.61) 151.18,30.48 C75.1
N102806393: length 1.8
  TOP w0.102: v3(150.13,30.78) 149.58,30.78 149.54,30.73 149.37,30.57 149.27,30.57 U4.M10
  BOTTOM w0.254: v3(150.13,30.78) 150.29,30.94 C81.1
N102824760: length 9
  TOP w0.127: U4.J6 v3(147.53,27.53)
  L3_PWR w0.254: v3(147.53,27.53) 146.86,26.86
  L3_PWR w0.305: v3(146.1,23.88) 146.1,24.51 146.86,25.27 146.86,26.86
  BOTTOM w0.254: v3(146.1,23.88) 145.68,24.3 C83.1 ; R216.2 144.4,24.56 145.05,24.3 C83.1 ; C83.1 R217.1 ; C89.1 v3(147.53,27.53)
N102954723:
  vias: v1(156.64,13.72) v1(156.64,12.83)
N102971023: length 1.3
  BOTTOM w0.102: U205.4 131.35,45.83 R219.2
N102971148: length 2.4
  BOTTOM w0.102: R49.2 R219.1 R223.2
N102972460: length 2.1
  BOTTOM w0.102: R260.1 R261.1 132.13,42.23 U205.2
N102974327: length 1.3
  TOP w0.102: U207.4 163.37,10.46 R224.1
N102974329: length 5.7
  TOP w0.102: R259.1 R226.2 160.83,13.46 160.83,12.83 160.32,12.32 160.32,11.43 160.45,11.3 U207.2
N102974984: length 1.5
  BOTTOM w0.102: R227.1 135.62,14.8 U208.4
N102974986: length 5.3
  BOTTOM w0.102: R244.1 R366.1 ; R366.1 R229.2 ; R366.1 134.54,13.21 134.29,13.46 U208.2
N102975340: length 4.9
  TOP w0.102: v1(7.87,49.28) 8.76,50.16 R368.1
  BOTTOM w0.102: v1(7.87,49.28) 7.88,49.29 R230.2
N102975342: length 1.3
  BOTTOM w0.102: R230.1 7.88,52.23 7.93,52.28 M3.1
N102975646: length 1.3
  BOTTOM w0.102: M4.1 9.64,4.66 R231.1
N102977151: length 1.2
  BOTTOM w0.102: R232.1 49.45,29.51 49.28,29.34 U209.6
N102977178: length 9.1
  TOP w0.102: U212.2 50.04,35.18 50.22,35.36 50.22,36.25 v1(50.55,36.58)
  BOTTOM w0.102: R232.2 49.45,32.56 49.92,33.03 49.92,35.95 v1(50.55,36.58) R236.1
N102981054: length 2.1
  BOTTOM w0.102: U209.2 50.24,27.99 R238.1 R237.2
N102981520: length 2.2
  TOP w0.102: v1(52.58,33.78) 51.83,34.53 U212.4
  BOTTOM w0.102: R235.1 v1(52.58,33.78)
N102982227: length 4.5
  TOP w0.102: R239.2 v1(1.52,51.31) R240.1
  BOTTOM w0.102: U210.2 1.67,53.23 1.52,53.09 v1(1.52,51.31)
N102982627: length 2.2
  BOTTOM w0.102: U211.2 4.22,3.81 R242.1 R241.2
N102983525: length 11.1
  TOP w0.102: R243.1 10.67,50.8 6.1,50.8 5.46,50.16 5.46,49.28 5.21,49.02 v1(3.43,49.02)
  BOTTOM w0.102: v1(3.43,49.02) 3.12,49.33 R234.2
N102983638: length 1.3
  TOP w0.102: R233.2 5.97,5.87 6.07,5.97 R367.1
N102984339: length 3
  BOTTOM w0.102: M3.4 9.65,53.17 R247.1 R245.1
N102985542: length 2.7
  BOTTOM w0.102: R362.1 161.34,4.65 161.69,4.3 M1.4
N102986885: length 1.5
  BOTTOM w0.102: M4.4 7.87,3.72 R254.1
N102988264: length 1.6
  BOTTOM w0.102: U209.4 48.21,28.22 47.83,28.22 R364.1
N102988273: length 152.9
  TOP w0.102: v1(8.29,8.83) 7.92,8.46 6.32,8.46 5.74,7.87 v1(5.46,7.87) 4.95,7.87 4.37,8.46 2.08,8.46 1.52,7.9 1.52,6.68 1.65,6.55 R363.2 ; R365.1 v1(49.91,40.77)
  BOTTOM w0.102: v1(5.46,7.87) 5.46,9.22 12.57,16.33 19.15,16.33 28.57,25.76 28.57,27.51 28.37,27.71 28.37,34.24 28.8,34.67 28.8,37.11 30.15,38.46 30.15,40.94 28.57,42.52 19.46,42.52 13.39,48.59 6.91,48.59 5.97,49.53 R255.1 5.99,50.27 R252.1 ; v1(8.29,8.83) 13.84,14.38 41.17,14.38 47.17,20.37 R364.2 46.41,28.62 46.41,34.82 47.64,36.06 47.64,36.54 49.4,38.3 49.4,40.26 v1(49.91,40.77)
N102988559: length 2.3
  TOP w0.102: U213.4 49.45,19.43 49.78,19.43 v1(50.42,20.07)
  BOTTOM w0.102: R256.2 v1(50.42,20.07)
N102988816: length 150.1
  TOP w0.102: v1(50.42,17.27) 48.87,15.72 16.97,15.72 16.74,15.95 15.19,15.95 14.1,14.86 11.05,14.86 v1(4.83,8.64)
  BOTTOM w0.102: U211.1 4.83,5.24 v1(4.83,8.64) 4.83,9.42 12.22,16.81 18.47,16.81 27.53,25.88 27.53,36.53 29.54,38.53 29.54,40.31 27.97,41.88 19.33,41.88 13.21,48.01 3.17,48.01 2.4,48.78 U210.1 ; R257.1 50.67,31.37 51.69,31.37 52.07,30.99 52.07,25.66 52.07,25.65 52.06,25.65 50.93,24.51 50.93,19.41 50.94,19.39 50.94,18.3 50.8,18.16 R256.1 v1(50.42,17.27)
N102989280: length 1.2
  BOTTOM w0.102: R257.2 50.34,29.04 U209.1
N102995385: length 4.2
  BOTTOM w0.102: U214.4 130.86,36.07 131.52,36.07 131.62,36.17 131.62,38.73 R260.2
N102999315: length 63.1
  TOP w0.102: v1(132.51,8.25) 132.51,9.91 132,10.41 132,15.11 129.16,17.96 129.16,40.59 129.34,40.77 v1(129.72,40.77) ; D2.A 143.17,4.46 143.94,3.68 145.08,3.68 145.85,4.45 148.13,4.45 149.01,5.32 SW64.2 149.01,6.26 v1(149.35,6.6)
  BOTTOM w0.102: v1(149.35,6.6) 148.84,6.1 144.83,6.1 144.15,6.78 140.27,6.78 140.23,6.82 140.22,6.82 139.36,7.67 136.73,7.67 136.5,7.44 133.72,7.44 133.29,7.87 132.89,7.87 v1(132.51,8.25) ; R262.1 130.23,40.26 v1(129.72,40.77)
N102999320: length 1.4
  BOTTOM w0.102: U214.6 130.99,38.09 R262.2
N102999809: length 1.8
  TOP w0.102: v1(142.29,2.03) D2.C
  BOTTOM w0.102: R263.1 v1(142.29,2.03)
N103006469: length 1.4
  TOP w0.102: U215.D3 v1(142.59,18.36)
  BOTTOM w0.127: v1(142.59,18.36) 142.1,17.87 R265.2
N103006492: length 1.4
  TOP w0.102: U215.D2 v1(142.59,19.36)
  BOTTOM w0.102: R266.2 v1(142.59,19.36)
N103006515: length 1.4
  TOP w0.102: v1(143.59,17.34) U215.C4
  BOTTOM w0.127: R267.2 143.56,17.34 v1(143.59,17.34)
N103006538: length 2.5
  TOP w0.102: U215.D4 v1(142.59,17.36)
  BOTTOM w0.127: v1(142.59,17.36) 142.5,16.99 142.5,16.56 142.58,16.37 R268.2
N103006561: length 1.8
  TOP w0.102: v1(142.09,16.11) U215.D5
  BOTTOM w0.102: R269.2 v1(142.09,16.11)
N103006584: length 1.4
  TOP w0.102: U215.E3 140.6,19.35 v1(140.6,19.36)
  BOTTOM w0.127: R270.2 v1(140.6,19.36)
N103006607: length 1.4
  TOP w0.102: U215.E2 v1(140.59,20.36)
  BOTTOM w0.127: R271.2 U215.E2 v1(140.59,20.36)
N103006630: length 1.4
  TOP w0.127: U215.E1 v1(140.59,21.36)
  BOTTOM w0.127: R272.2 U215.E1 v1(140.59,21.36)
N103006767: length 2.1
  TOP w0.102: U215.A3 v1(145.59,18.36)
  BOTTOM w0.127: R278.2 v1(145.59,18.36) R282.2
N103006790: length 2.1
  TOP w0.102: U215.B2 v1(144.59,20.36)
  BOTTOM w0.102: R285.1 v1(144.59,20.36) R279.2
N103007378: length 4.3
  TOP w0.102: U215.C2 143.43,20.2 143.43,21.03 143.09,21.86 v1(142.59,22.36) 142.6,22.36 TP202.1
  BOTTOM w0.102: R280.2 v1(142.59,22.36)
N103007771: length 1.4
  TOP w0.102: U215.C3 v1(143.59,18.36)
  BOTTOM w0.127: R281.2 143.59,18.35 v1(143.59,18.36)
N103012825: length 3.9
  TOP w0.102: v1(41.78,33.15) 41.68,33.53 J8.64
  BOTTOM w0.102: C227.1 R218.2 42.04,32.53 v1(41.78,33.15)
N103019057: length 40.3
  TOP w0.102: v1(57.66,21.59) 45.09,21.59 v1(44.45,22.23) ; J8.20 30.68,33.6 30.52,33.44 30.52,32.74 30.62,32.64 42.29,32.64 v1(42.8,33.15)
  BOTTOM w0.102: R300.1 v1(57.66,21.59) ; v1(42.8,33.15) 43.43,32.51 43.43,23.24 v1(44.45,22.23)
N103019687: length 24.6
  TOP w0.102: J8.21 30.93,42.98 30.38,43.54 23.88,43.54 22.17,41.83 18.85,41.83 v1(17.02,40.01)
  BOTTOM w0.102: v1(17.02,40.01) 16.26,39.24 R304.1
N103019945: length 47.5
  TOP w0.102: v1(40.39,23.88) 40.46,23.88 40.56,23.77 56.24,23.77 56.39,23.62 59.56,23.62 60.07,24.13 71.86,24.13 72.01,24.28 73.08,24.28 73.56,24.77 v1(75.56,24.77) ; J8.56 39.68,33.47 v1(40.01,33.15)
  BOTTOM w0.102: R318.2 v1(75.56,24.77) ; v1(40.01,33.15) 40.01,26.54 40.39,26.16 v1(40.39,23.88)
N103019994: length 48.2
  TOP w0.102: v1(38.86,33.15) 39.18,33.46 J8.54 ; v1(38.86,25.78) 39.29,25.35 54.76,25.35 55.09,25.02 58.34,25.02 60.43,27.1 63.88,27.1 64.9,26.09 73.96,26.09 74.42,26.54 v1(75.56,26.54)
  BOTTOM w0.102: R319.2 v1(75.56,26.54) ; v1(38.86,33.15) v1(38.86,25.78)
N103022078: length 3.6
  BOTTOM w0.102: R294.2 69.3,27.01 v4(69.3,26.62) 68.9,26.46 U221.8
N103022219: length 2.8
  BOTTOM w0.102: R296.1 R379.1 R378.2 R295.1
N103022552: length 4
  BOTTOM w0.102: U221.13 69.02,23.21 v4(69.57,22.66) 70.13,22.1 R301.2 R297.2
N103022554: length 3.5
  BOTTOM w0.102: U221.12 68,23.88 R306.2 R298.2
N103023474: length 3.6
  BOTTOM w0.102: R307.2 R309.2 70.36,24.51 v4(69.47,24.51) U221.11
N103024377: length 2.8
  BOTTOM w0.102: R308.1 R381.1 R380.2 R310.1
N103024546: length 4.1
  BOTTOM w0.102: R311.2 R339.2 69.98,25.91 69.75,25.91 v4(69.47,25.63) 69,25.16 U221.10
N103030751: length 4.1
  BOTTOM w0.102: R317.1 R313.2 65.91,10.92 66.16,10.68 U3.5
N103030787: length 1.5
  BOTTOM w0.102: C276.1 65.65,9.66 U3.6
N103030825: length 15.1
  TOP w0.102: v1(64.13,11.56) 53.34,11.56 53.21,11.68 TP209.1 R314.2
  BOTTOM w0.102: v1(64.13,11.56) 64.59,11.56 U3.1
N103030906: length 12.6
  BOTTOM w0.102: TP208.1 53.09,9.91 R313.3
N103038120: length 3.8
  TOP w0.102: J8.50 38.23,34.52 v1(38.23,35.81)
  BOTTOM w0.102: R316.2 37.59,36.96 37.72,36.83 R361.1 v1(38.23,35.81)
N103040281: length 4
  TOP w0.356: C70.1 13.11,39.53 U2.23
  TOP w0.508: L61.1 15.4,39.5 U2.23
N103040289: length 1.6
  TOP w0.508: U2.21 15.48,37.51 L61.2
N103040293: length 3.7
  TOP w0.381: U2.22 v1(13.24,38.41)
  BOTTOM w0.381: 14.99,38.86 R357.2 C60.1 v1(13.24,38.41)
N103040458: length 1.9
  TOP w0.102: U2.13 15.2,30.31 v1(15.24,30.35)
  BOTTOM w0.102: R336.2 v1(15.24,30.35)
N103040524: length 5.3
  TOP w0.102: R325.2 16.89,38.23 16.89,37.08 15.52,35.71 U2.19
N103040539: length 6.3
  TOP w0.102: U2.14 16.16,31.21 16.64,30.73 16.64,29.21 17.53,28.32 R326.2
N103040548: length 4.7
  TOP w0.102: R327.2 17.02,30.23 17.02,30.99 15.9,32.11 U2.15
N103040555: length 3.7
  TOP w0.102: U2.16 16.52,33.01 R328.2
N103040569: length 3.5
  TOP w0.102: R329.2 16.51,34.29 16.13,33.91 U2.17
N103040633: length 1.8
  TOP w0.635: C1.2 C2.1 R2.2
N103040687: length 2.8
  TOP w0.102: U2.24 12.32,39.59 R323.1 12.32,41.24 R322.1
N103057784: length 4
  TOP w0.102: R324.2 15.76,34.81 U2.18
N103058128: length 19.5
  TOP w0.102: R334.1 v1(23.24,27.43) ; J8.17 29.93,40.29 29.26,39.62 28.7,39.62 v1(28.19,39.12)
  BOTTOM w0.102: v1(28.19,39.12) 26.82,37.74 26.82,36.73 24.16,34.06 24.16,31.39 22.71,29.95 22.71,29.34 22.89,29.16 23.16,29.16 23.62,28.7 23.62,27.81 v1(23.24,27.43)
N103058131: length 11.9
  TOP w0.102: v1(23.98,39.12) 24.53,39.67 25.77,39.67 26.24,40.13 27.32,40.13 27.93,40.74 J8.9 ; R330.1 v1(23.24,34.29)
  BOTTOM w0.102: v1(23.24,34.29) 23.84,34.89 23.84,38.06 23.98,38.2 v1(23.98,39.12)
N103058134: length 13.9
  TOP w0.102: R331.1 v1(23.24,32) ; v1(25.53,39.24) 26.06,39.24 26.59,39.78 27.46,39.78 28.43,40.74 J8.11
  BOTTOM w0.102: v1(25.53,39.24) 24.2,37.91 24.2,34.6 23.8,34.21 23.8,32.56 v1(23.24,32)
N103058137: length 11.9
  TOP w0.102: v1(27.18,39.12) 27.48,39.42 27.61,39.42 28.93,40.74 J8.13 ; R332.1 v1(23.24,36.58)
  BOTTOM w0.102: v1(27.18,39.12) 26.54,39.75 23.57,39.75 23.32,39.5 23.32,38.66 23.48,38.49 23.48,37.45 23.24,37.21 v1(23.24,36.58)
N103058140: length 16.4
  TOP w0.102: R335.1 v1(23.24,29.72) ; J8.19 30.43,40.26 29.29,39.12 v1(28.96,39.12)
  BOTTOM w0.102: v1(23.24,29.72) 24.51,30.99 24.51,33.78 27.18,36.45 27.18,37.34 v1(28.96,39.12)
N103058143: length 11.3
  TOP w0.102: J8.15 29.43,43.08 29.33,43.18 24.31,43.18 22.73,41.61 22.73,39.78 R333.1
N103059335: length 3.2
  TOP w0.381: U2.34 v1(2.03,38.41)
  BOTTOM w0.381: R337.1 2.47,37.97 v1(2.03,38.41) 2.61,38.99 R338.2
N103060267: length 3
  TOP w0.102: v1(15.21,29.21) 15.02,29.41 U2.12
  BOTTOM w0.102: v1(15.21,29.21) 15.83,29.46 R341.2 R340.1
N103061025: length 38.6
  TOP w0.102: v1(2.03,32.11) U2.41 ; v1(19.68,24.79) 32.41,24.79 v1(33.66,26.04)
  BOTTOM w0.102: v1(2.03,32.11) 1.52,31.6 1.52,30.96 1.88,30.61 3.17,30.61 3.43,30.35 9.04,30.35 11.52,27.88 13.8,27.88 16.89,24.79 v1(19.68,24.79) ; R345.1 v1(33.66,26.04)
N103061028: length 38.9
  TOP w0.102: v1(20.95,24.38) 33.66,24.38 v1(35.31,26.04) ; U2.44 2.13,29.41 2.03,29.51 v1(2.03,29.97)
  BOTTOM w0.102: R342.1 v1(35.31,26.04) ; v1(20.95,24.38) 20.46,24.18 16.99,24.18 13.65,27.52 11.18,27.52 8.73,29.97 v1(2.03,29.97)
N103061031: length 33.3
  TOP w0.102: v1(32,26.04) 31.24,25.27 v1(20.95,25.27) ; v1(4.06,30.86) 4.06,30.48 3.89,30.31 U2.43
  BOTTOM w0.102: v1(20.95,25.27) 20.46,25.48 19.58,25.48 19.25,25.15 17.03,25.15 13.95,28.23 11.67,28.23 9.04,30.86 v1(4.06,30.86) ; R343.1 v1(32,26.04)
N103061034: length 33
  TOP w0.102: v1(18.92,25.68) 20.09,25.68 20.19,25.78 30.1,25.78 v1(30.35,26.04) ; v1(2.03,31.21) U2.42
  BOTTOM w0.102: v1(18.92,25.68) 18.56,25.53 17.16,25.53 14.09,28.59 11.82,28.59 9.04,31.37 3.14,31.37 2.98,31.21 v1(2.03,31.21) ; R344.1 v1(30.35,26.04)
N103061599: length 3.6
  TOP w0.102: J8.32 33.68,33.93 32.89,33.15 v1(32,33.15)
  BOTTOM w0.102: R347.1 v1(32,33.15)
N103061602: length 2.7
  TOP w0.102: J8.34 34.18,33.42 33.91,33.15 v1(33.66,33.15)
  BOTTOM w0.102: R348.1 v1(33.66,33.15)
N103061605: length 2.6
  TOP w0.102: v1(30.99,33.15) 31.18,33.61 J8.22
  BOTTOM w0.102: R346.1 v1(30.99,33.15)
N103061608: length 2.8
  TOP w0.102: v1(35.31,33.15) 34.92,33.15 34.68,33.39 J8.36
  BOTTOM w0.102: R349.1 v1(35.31,33.15)
N103061936: length 53.9
  TOP w0.102: v1(9.54,27.3) U2.7 ; v1(14.22,23.5) 15.44,23.5 16.97,21.97 42.52,21.97 43.92,20.57 v1(57.66,20.57)
  BOTTOM w0.102: R352.1 v1(57.66,20.57) ; v1(14.22,23.5) 13.59,24.13 10.92,24.13 9.54,25.52 v1(9.54,27.3)
N103074237: length 2
  TOP w0.102: R363.1 v1(1.65,3.81)
  BOTTOM w0.102: v1(1.65,3.81) 2.38,3.81 U211.4
N103074547: length 3.4
  BOTTOM w0.102: R255.2 5.97,52.6 5.34,53.23 U210.4
N103079715: length 2
  TOP w0.102: R228.1 v1(10.26,7.52)
  BOTTOM w0.102: R231.2 v1(10.26,7.52)
N103090099: length 19.1
  TOP w0.102: v1(142.54,13.08) 143.65,11.98 U216.2
  BOTTOM w0.102: v1(142.54,13.08) 142.25,13.38 141.85,13.54 141.8,13.68 141.87,13.85 141.82,13.99 141.63,14.06 141.49,14.01 141.42,13.83 141.29,13.78 140.32,14.18 140.18,14.12 140.05,13.81 139.92,13.76 139.73,13.83 139.68,13.97 139.81,14.28 139.75,14.41 139.02,14.72 138.28,15.46 138.28,19.39 138.38,19.49 138.76,19.49 138.86,19.6 138.86,19.8 138.76,19.9 138.53,19.9 138.43,20 138.43,20.21 138.53,20.31 138.76,20.31 138.86,20.41 138.86,20.61 138.76,20.71 138.53,20.71 138.43,20.82 138.43,21.29 139.27,22.12 R273.2
N103090100: length 17
  TOP w0.102: U216.5 139.64,15.04 139.56,15.11 138.61,15.11 138.23,15.49 138.23,17.78 138.3,17.86 138.66,17.86 138.73,17.78 138.73,15.82 138.84,15.72 139.94,15.72 140.89,14.77 v1(140.89,14.48)
  BOTTOM w0.102: v1(140.89,14.48) 140.48,14.65 140.43,14.78 140.53,15.03 140.48,15.16 140.29,15.24 140.16,15.18 140.05,14.94 139.74,14.8 139.23,15.01 138.83,15.42 138.83,15.65 138.93,15.75 139.12,15.75 139.22,15.85 139.22,16.13 139.12,16.23 138.73,16.23 138.63,16.33 138.63,16.74 138.73,16.84 139.32,16.84 139.42,16.94 139.42,17.14 139.32,17.24 139.12,17.24 139.01,17.34 R264.2
N103090101: length 15.8
  TOP w0.102: U216.7 v1(138.34,11.98)
  BOTTOM w0.102: R275.2 143.13,12.45 143.03,12.34 142.57,12.34 142.47,12.24 142.47,11.53 142.37,11.43 141.68,11.43 141.58,11.53 141.58,12.59 141.47,12.69 141.33,12.69 141.23,12.59 141.23,12.17 141.13,12.06 140.92,12.06 140.82,12.17 140.82,12.59 140.72,12.69 140.52,12.69 140.42,12.59 140.42,11.48 140.31,11.38 140.11,11.38 140.01,11.48 140.01,12.59 139.91,12.69 139.7,12.69 139.6,12.59 139.6,12.36 139.5,12.25 138.89,12.25 138.79,12.15 138.79,11.95 138.89,11.85 139.5,11.85 139.6,11.75 139.6,11.51 139.5,11.4 138.44,11.4 138.34,11.51 v1(138.34,11.98)
N103090102: length 14.6
  TOP w0.127: U216.3 v1(146.47,13.25)
  BOTTOM w0.102: v1(146.47,13.25) 146.47,12.61 146.16,12.29 145.68,12.29 145.58,12.4 145.58,13.69 145.68,13.79 146.33,13.79 146.43,13.89 146.43,14.1 146.33,14.2 145.68,14.2 145.58,14.3 145.58,14.53 145.48,14.63 145.28,14.63 145.17,14.53 145.17,13.59 145.07,13.49 144.65,13.49 144.55,13.39 144.55,13.18 144.65,13.08 145.07,13.08 145.17,12.98 145.17,11.81 145.07,11.71 144.2,11.71 144.09,11.81 144.09,13.61 R274.2
N103091093: length 19.5
  TOP w0.127: U216.1 v1(143.68,10.71)
  BOTTOM w0.102: R276.1 147.34,17.5 147.34,17.36 146.98,17 146.98,16.85 147.12,16.71 147.27,16.71 147.63,17.07 147.77,17.07 148.03,16.81 148.03,16.53 147.93,16.43 147.47,16.43 147.37,16.32 147.37,16.12 147.47,16.02 147.93,16.02 148.03,15.92 148.03,15.72 147.93,15.61 147.55,15.61 147.45,15.51 147.45,15.31 147.55,15.21 147.93,15.21 148.03,15.11 148.03,14.9 147.93,14.8 147.55,14.8 147.45,14.7 147.45,14.5 147.55,14.39 147.93,14.39 148.03,14.29 148.03,13.43 147.84,13.24 147.69,13.24 147.3,13.63 147.16,13.63 147.01,13.49 147.01,13.34 147.41,12.95 147.41,12.73 146.72,12.04 146.72,11.9 146.93,11.69 146.93,11.55 146.78,11.4 146.64,11.4 146.43,11.61 146.29,11.61 146.14,11.47 146.14,11.33 146.35,11.11 146.35,10.97 146.21,10.83 146.07,10.83 145.85,11.04 145.71,11.04 145.38,10.71 v1(143.68,10.71)
  BOTTOM w0.127: R283.2 v1(143.68,10.71)
